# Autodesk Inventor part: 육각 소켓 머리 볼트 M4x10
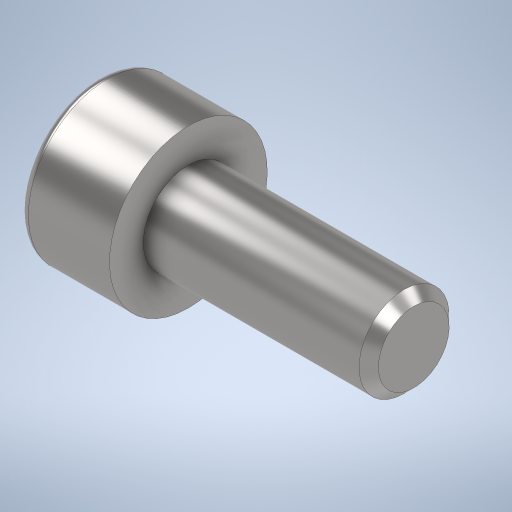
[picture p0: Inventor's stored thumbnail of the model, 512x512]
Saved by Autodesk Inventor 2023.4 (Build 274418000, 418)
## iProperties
Created: 2024-05
Part Number: 육각 소켓 머리 볼트 M4x10
Material: 강철, 연강
Description: 6각머리 태핑 나사
Document SubType Name: Modeling
Designer: user
Density: 7.85 g/cm^3
Appearance: 기본값
Author: jhkim
Sending System: Autodesk Inventor 2025
Preprocessor: ST-DEVELOPER v20
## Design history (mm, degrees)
feature "Solid1"
node "솔리드1"
